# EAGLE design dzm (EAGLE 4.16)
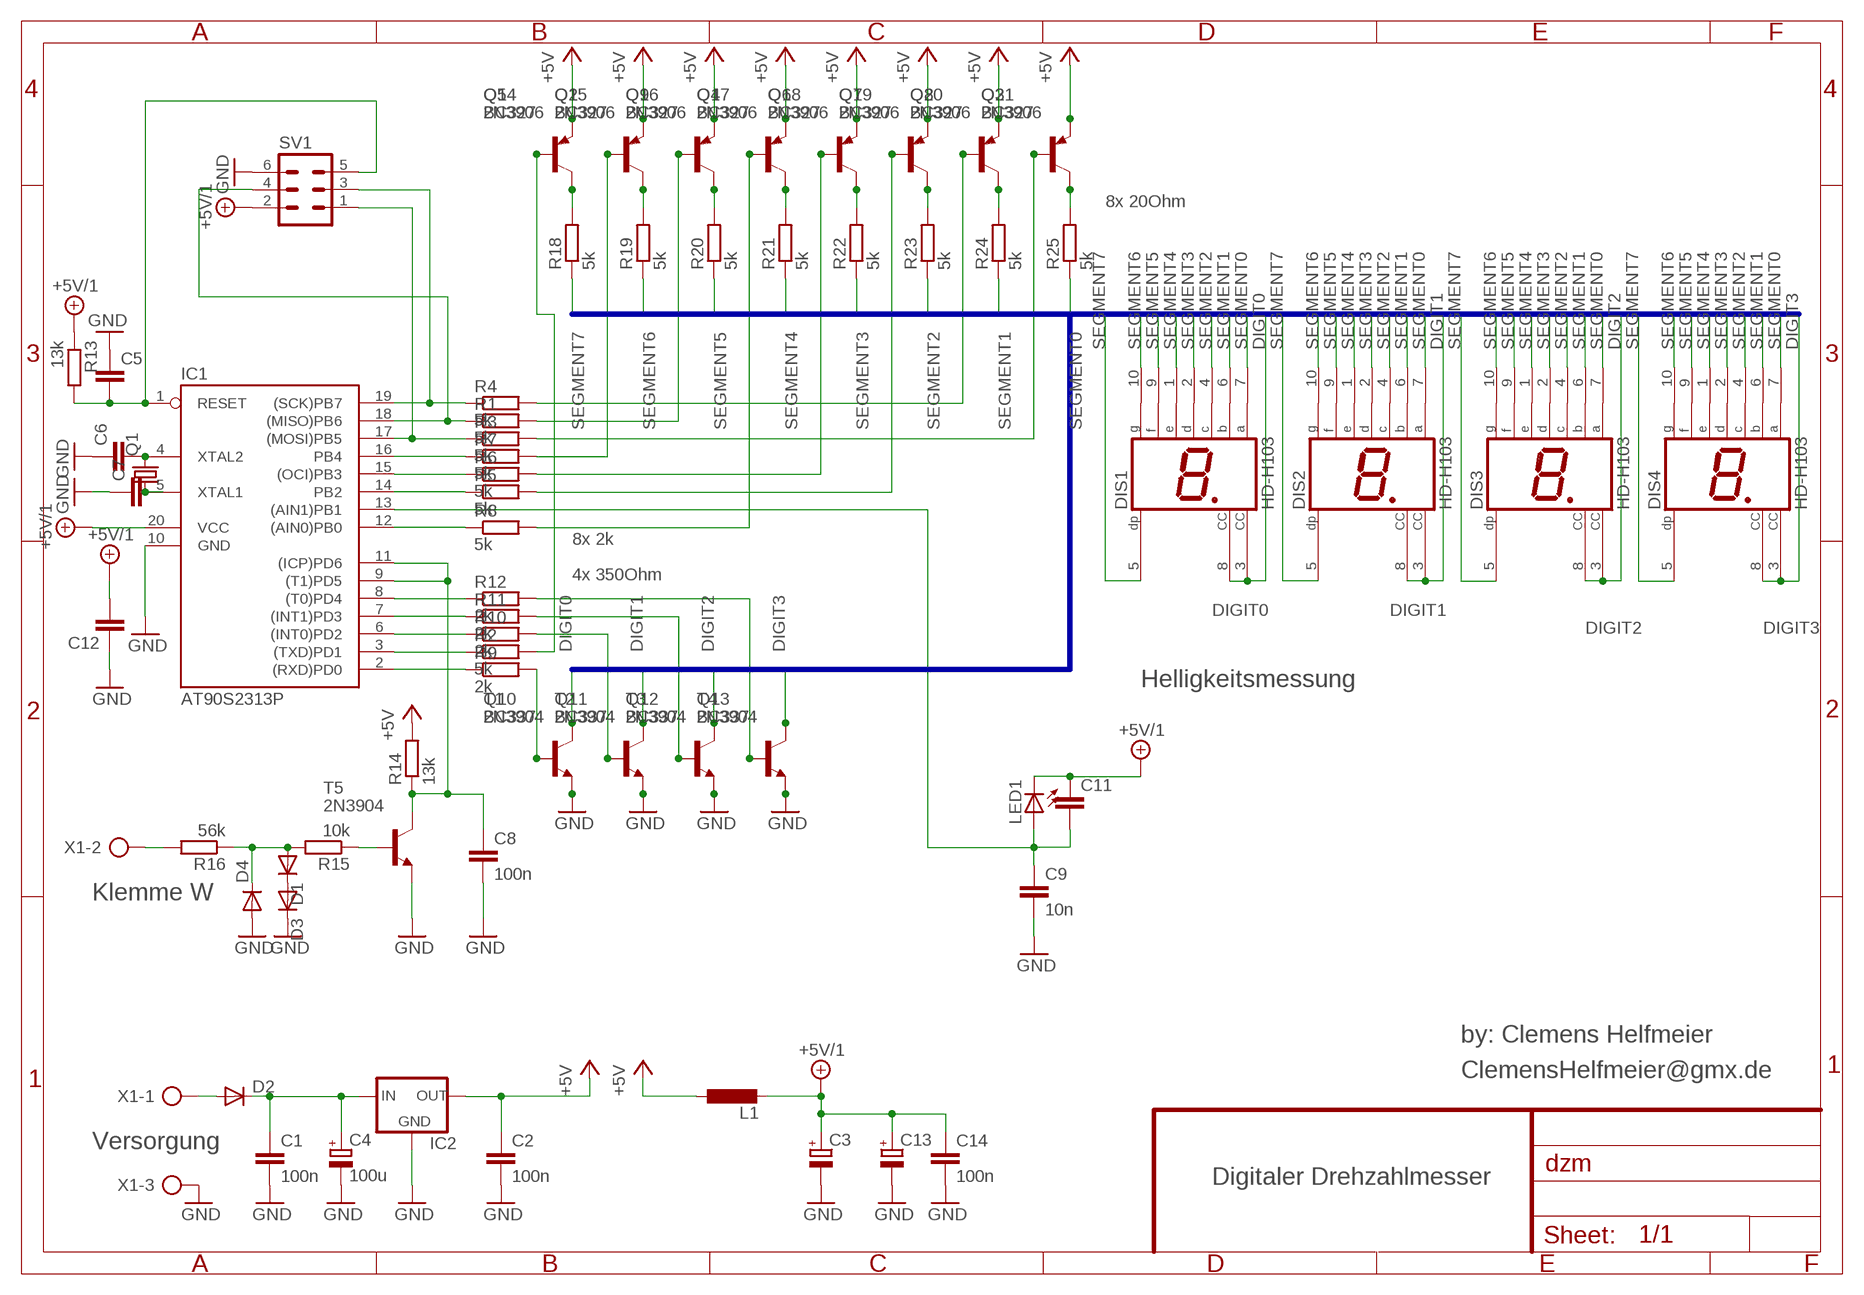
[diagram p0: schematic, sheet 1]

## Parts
C1  100n  C-EU025-024X044  [C025-024X044]
C2  100n  C-EU025-024X044  [C025-024X044]
C3  CPOL-EUE5-10.5  [E5-10,5]
C4  100u  CPOL-EUE5-13  [E5-13]
C5  C-EU025-024X044  [C025-024X044]
C6  C-EU025-024X044  [C025-024X044]
C7  C-EU025-024X044  [C025-024X044]
C8  100n  C-EU025-024X044  [C025-024X044]
C9  10n  C-EU025-024X044  [C025-024X044]
C11  C-EU050-024X044  [C050-024X044]
C12  C-EU025-024X044  [C025-024X044]
C13  CPOL-EUE2.5-7  [E2,5-7]
C14  100n  C-EU025-024X044  [C025-024X044]
D1  DIODE-D-5  [D-5]
D2  DIODE-D-7.5  [D-7.5]
D3  DIODE-D-5  [D-5]
D4  DIODE-D-5  [D-5]
DIS1  HD-H103  [HDSP-M]
DIS2  HD-H103  [HDSP-M]
DIS3  HD-H103  [HDSP-M]
DIS4  HD-H103  [HDSP-M]
IC1  AT90S2313P  [DIL20]
IC2  78XXS  [78XXS]
L1  L-EU0207/5V  [0207/5V]
LED1  LED5MM  [LED5MM]
Q1  CRYTALHC49S  [HC49/S]
Q2  2N3906  [TO92]
Q3  2N3906  [TO92]
Q4  2N3906  [TO92]
Q5  2N3906  [TO92]
Q6  2N3906  [TO92]
Q7  2N3906  [TO92]
Q8  2N3906  [TO92]
Q9  2N3906  [TO92]
Q10  BC337  [TO92]
Q11  BC337  [TO92]
Q12  BC337  [TO92]
Q13  BC337  [TO92]
Q14  BC327  [TO92]
Q15  BC327  [TO92]
Q16  BC327  [TO92]
Q17  BC327  [TO92]
Q18  BC327  [TO92]
Q19  BC327  [TO92]
Q20  BC327  [TO92]
Q21  BC327  [TO92]
R1  5k  R-EU_0207/12  [0207/12]
R2  5k  R-EU_0207/7  [0207/7]
R3  5k  R-EU_0207/12  [0207/12]
R4  5k  R-EU_0207/12  [0207/12]
R5  5k  R-EU_0207/7  [0207/7]
R6  5k  R-EU_0207/7  [0207/7]
R7  5k  R-EU_0207/10  [0207/10]
R8  5k  R-EU_0207/7  [0207/7]
R9  2k  R-EU_0207/7  [0207/7]
R10  2k  R-EU_0207/2V  [0207/2V]
R11  2k  R-EU_0207/2V  [0207/2V]
R12  2k  R-EU_0207/2V  [0207/2V]
R13  13k  R-EU_0207/7  [0207/7]
R14  13k  R-EU_0207/7  [0207/7]
R15  10k  R-EU_0207/7  [0207/7]
R16  56k  R-EU_0207/7  [0207/7]
R18  5k  R-EU_0207/2V  [0207/2V]
R19  5k  R-EU_0207/2V  [0207/2V]
R20  5k  R-EU_0207/2V  [0207/2V]
R21  5k  R-EU_0207/2V  [0207/2V]
R22  5k  R-EU_0207/2V  [0207/2V]
R23  5k  R-EU_0207/2V  [0207/2V]
R24  5k  R-EU_0207/2V  [0207/2V]
R25  5k  R-EU_0207/2V  [0207/2V]
SV1  MA03-2  [MA03-2]
T1  2N3904  [TO92]
T2  2N3904  [TO92]
T3  2N3904  [TO92]
T4  2N3904  [TO92]
T5  2N3904  [TO92]
X1  AK300/3  [AK300/3]

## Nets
+5V: C2.1 IC2.OUT L1.1 Q2.3(E) Q3.3(E) Q4.3(E) Q5.3(E) Q6.3(E) Q7.3(E) Q8.3(E) Q9.3(E) Q14.1(E) Q15.1(E) Q16.1(E) Q17.1(E) Q18.1(E) Q19.1(E) Q20.1(E) Q21.1(E) R14.2
+5V/1: C3.+ C11.1 C12.2 C13.+ C14.1 IC1.20(VCC) L1.2 LED1.K(C) R13.1 SV1.2
DIGIT0: DIS1.3(CC) DIS1.8(CC) Q10.3(C) T1.1(C)
DIGIT1: DIS2.3(CC) DIS2.8(CC) Q11.3(C) T2.1(C)
DIGIT2: DIS3.3(CC) DIS3.8(CC) Q12.3(C) T3.1(C)
DIGIT3: DIS4.3(CC) DIS4.8(CC) Q13.3(C) T4.1(C)
GND: C1.2 C2.2 C3.- C4.- C5.1 C6.1 C7.1 C8.2 C9.2 C12.1 C13.- C14.2 D3.C D4.A IC1.10(GND) IC2.GND Q10.1(E) Q11.1(E) Q12.1(E) Q13.1(E) SV1.6 T1.3(E) T2.3(E) T3.3(E) T4.3(E) T5.3(E) X1.3
N$1: D2.A X1.1
N$2: IC1.16(PB4) R7.1
N$3: IC1.17((MOSI)PB5) R3.1 SV1.1
N$4: IC1.6((INT0)PD2) R10.1
N$5: IC1.15((OCI)PB3) R6.1
N$6: IC1.14(PB2) R5.1
N$7: IC1.18((MISO)PB6) R1.1 SV1.4
N$8: IC1.12((AIN0)PB0) R8.1
N$9: IC1.7((INT1)PD3) R11.1
N$10: IC1.8((T0)PD4) R12.1
N$11: IC1.3((TXD)PD1) R2.1
N$12: Q10.2(B) R9.2 T1.2(B)
N$13: Q11.2(B) R10.2 T2.2(B)
N$14: Q12.2(B) R11.2 T3.2(B)
N$15: Q13.2(B) R12.2 T4.2(B)
N$16: Q5.2(B) Q14.2(B) R2.2
N$17: Q2.2(B) Q15.2(B) R7.2
N$18: Q3.2(B) Q21.2(B) R3.2
N$19: C1.1 C4.+ D2.C IC2.IN
N$20: Q4.2(B) Q17.2(B) R8.2
N$21: IC1.19((SCK)PB7) R4.1 SV1.3
N$22: C5.2 IC1.1(RESET) R13.2 SV1.5
N$23: C6.2 IC1.4(XTAL2) Q1.2
N$24: C7.2 IC1.5(XTAL1) Q1.1
N$25: IC1.2((RXD)PD0) R9.1
N$26: Q6.2(B) Q18.2(B) R6.2
N$27: Q7.2(B) Q19.2(B) R5.2
N$28: Q8.2(B) Q20.2(B) R4.2
N$29: Q9.2(B) Q16.2(B) R1.2
N$30: C8.1 IC1.9((T1)PD5) IC1.11((ICP)PD6) R14.1 T5.1(C)
N$31: R15.1 T5.2(B)
N$32: D1.C D3.A
N$33: R16.2 X1.2
N$34: D1.A D4.C R15.2 R16.1
N$35: C9.1 C11.2 IC1.13((AIN1)PB1) LED1.A
N$37: Q5.1(C) Q14.3(C) R18.2
N$38: Q2.1(C) Q15.3(C) R19.2
N$39: Q3.1(C) Q21.3(C) R25.2
N$40: Q4.1(C) Q17.3(C) R21.2
N$41: Q6.1(C) Q18.3(C) R22.2
N$42: Q7.1(C) Q19.3(C) R23.2
N$43: Q8.1(C) Q20.3(C) R24.2
N$44: Q9.1(C) Q16.3(C) R20.2
SEGMENT0: DIS1.7(A) DIS2.7(A) DIS3.7(A) DIS4.7(A) R25.1
SEGMENT1: DIS1.6(B) DIS2.6(B) DIS3.6(B) DIS4.6(B) R24.1
SEGMENT2: DIS1.4(C) DIS2.4(C) DIS3.4(C) DIS4.4(C) R23.1
SEGMENT3: DIS1.2(D) DIS2.2(D) DIS3.2(D) DIS4.2(D) R22.1
SEGMENT4: DIS1.1(E) DIS2.1(E) DIS3.1(E) DIS4.1(E) R21.1
SEGMENT5: DIS1.9(F) DIS2.9(F) DIS3.9(F) DIS4.9(F) R20.1
SEGMENT6: DIS1.10(G) DIS2.10(G) DIS3.10(G) DIS4.10(G) R19.1
SEGMENT7: DIS1.5(DP) DIS2.5(DP) DIS3.5(DP) DIS4.5(DP) R18.1

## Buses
DISPLAY:SEGMENT[0..7],DIGIT[0..3]

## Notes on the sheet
- 8x 20Ohm
- 8x 2k
- 4x 350Ohm
- Helligkeitsmessung
- Klemme W
- by: Clemens Helfmeier
- ClemensHelfmeier@gmx.de
- Versorgung
- Digitaler Drehzahlmesser

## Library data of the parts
C1 C2 C5-C9 C11 C12 C14 = rcl:C-EU: CAPACITOR, European symbol
C3 C4 C13 = rcl:CPOL-EU: POLARIZED CAPACITOR, European symbol
D1-D4 = diode:DIODE-: DIODE
DIS1-DIS4 = display-hp:HD-H103: LED DISPLAY 1-character 7 segment, decimal point right
IC1 = atmel:AT90S2313: MICROCONTROLLER 2 Kbytes FLASH 128 bytes SRAM 128 bytes EEPROM UART
IC2 = v-reg:78XXS: VOLTAGE REGULATOR
L1 = rcl:L-EU: INDUCTOR, European symbol
LED1 = led:LED: LED
Q1 = crystal:CRYTAL: CRYSTAL
Q2-Q9 = transistor-pnp:2N3906: PNP Transistor
Q10-Q13 = transistor-npn:BC337*: NPN Transistor
Q14-Q21 = transistor-pnp:BC327: PNP Transistor
R1-R16 R18-R25 = rcl:R-EU_: RESISTOR, European symbol
SV1 = con-lstb:MA03-2: PIN HEADER
T1-T5 = transistor:2N3904: NPN TRANSISTOR
X1 = con-ptr500:AK300/3: CONNECTOR

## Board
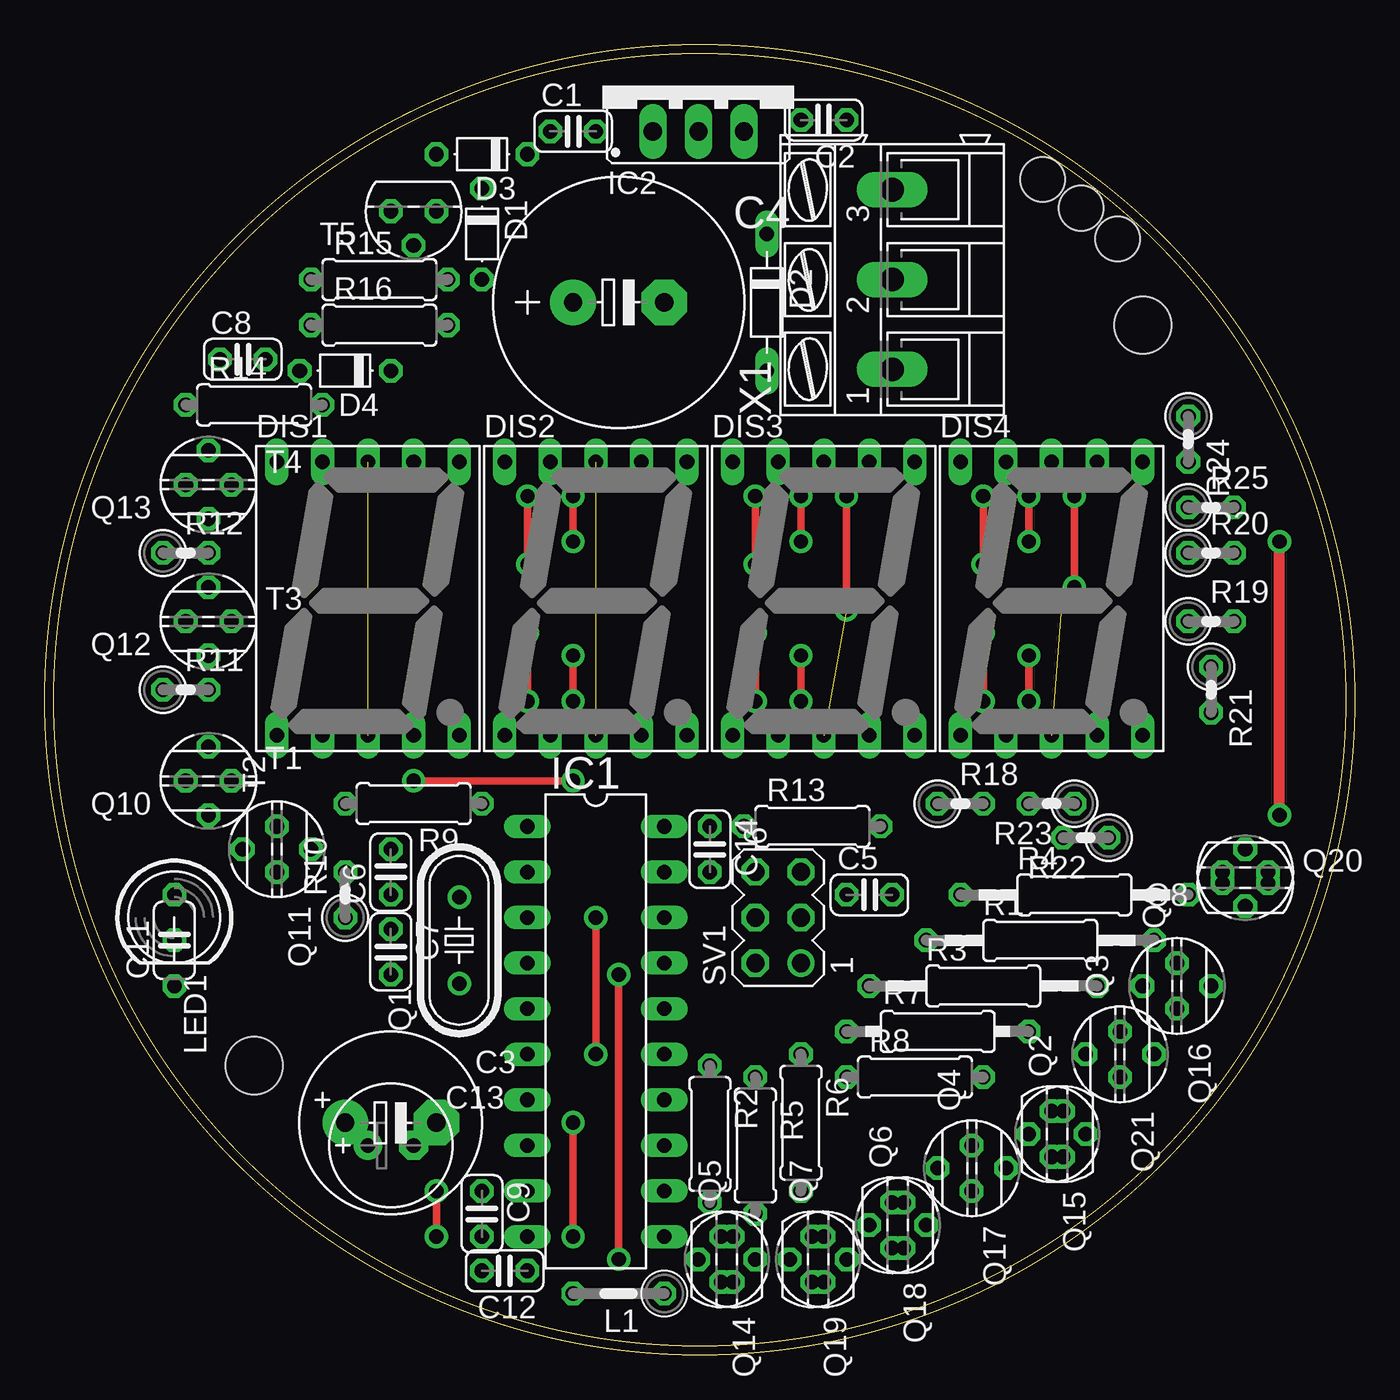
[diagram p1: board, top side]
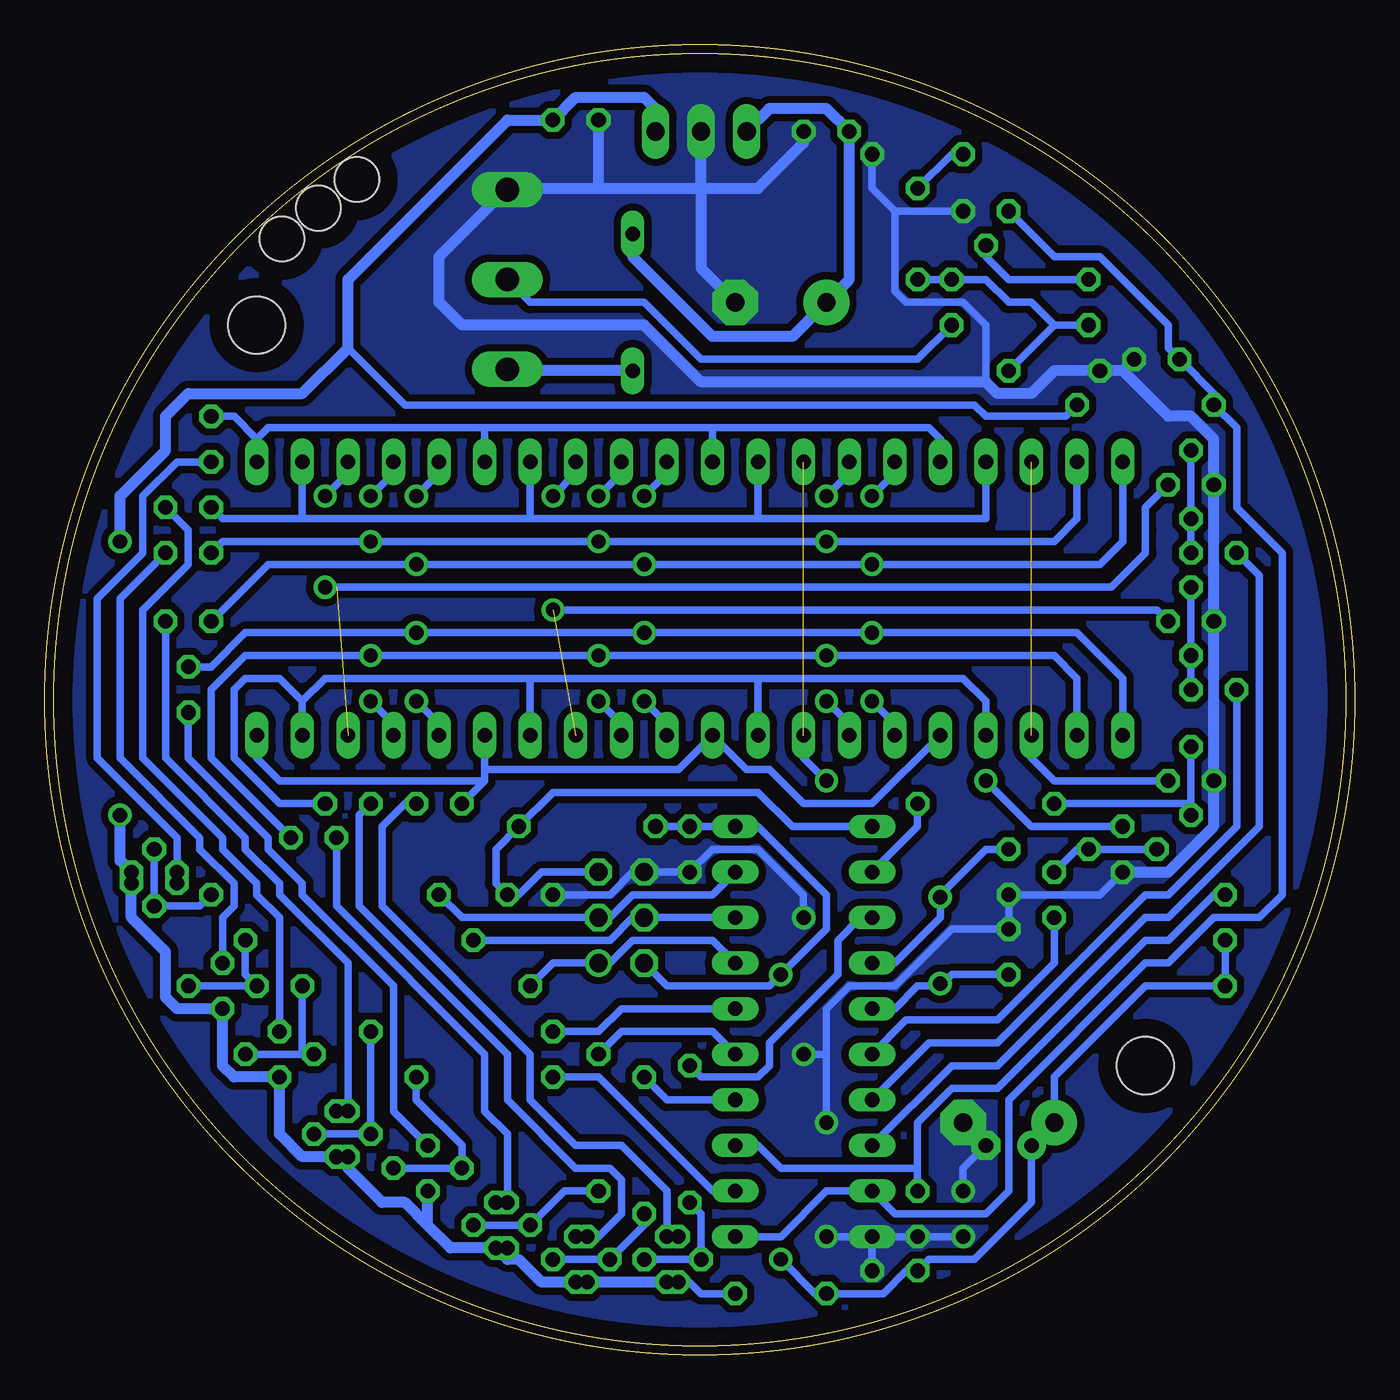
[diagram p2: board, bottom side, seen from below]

Size 73 x 73 mm. Coordinates in mm from the lower left corner, seen from the top.
Outline: circle at 36.5,36.5 radius 36.5
Outline: circle at 36.5,36.5 radius 36
Copper layers (1*16): Top 0.035mm / dielectric 1.5mm / Bottom 0.035mm
Design rules "homebrew": minimum track width 16mil, minimum drill 0.8mm, track to track 0.25mm, track to pad 0.25mm, pad to pad 0.25mm, via to via 0.25mm, smd to smd 8mil, copper to edge 40mil, drill to drill 0.2mm, minimum pad ring 0.25mm, minimum via ring 0.25mm, stop-mask expansion 0.15mm, vias tented up to drill 0mil, thermal gap 10mil
Holes 3.2 mm at 61.19,57.38 11.66,16.11
Holes 2.5 mm at 55.61,65.5 57.75,63.9 59.79,62.19

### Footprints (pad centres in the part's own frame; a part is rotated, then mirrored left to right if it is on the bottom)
C025-024X044 = drill 0.813 octagon: 1 -1.27,0; 2 1.27,0
E5-10,5 = drill 1.016 pad 2.54 round: + -2.54,0 | drill 1.016 pad 2.54 octagon: - 2.54,0
E5-13 = drill 1.016 pad 2.54 round: + -2.54,0 | drill 1.016 pad 2.54 octagon: - 2.54,0
C050-024X044 = drill 0.813 octagon: 1 -2.54,0; 2 2.54,0
E2,5-7 = drill 0.813 pad 1.6 round: + -1.27,0 | drill 0.813 pad 1.6 octagon: - 1.27,0
D-5 = drill 0.813 octagon: A 2.54,0; C -2.54,0
D-7.5 = drill 0.813 long: A 3.81,0; C -3.81,0
HDSP-M = drill 0.813 long: 1 -5.08,-7.62; 2 -2.54,-7.62; 3 0,-7.62; 4 2.54,-7.62; 5 5.08,-7.62; 6 5.08,7.62; 7 2.54,7.62; 8 0,7.62; 9 -2.54,7.62; 10 -5.08,7.62
DIL20 = drill 0.813 long: 1 -11.43,-3.81; 2 -8.89,-3.81; 3 -6.35,-3.81; 4 -3.81,-3.81; 5 -1.27,-3.81; 6 1.27,-3.81; 7 3.81,-3.81; 8 6.35,-3.81; 9 8.89,-3.81; 10 11.43,-3.81; 11 11.43,3.81; 12 8.89,3.81; 13 6.35,3.81; 14 3.81,3.81; 15 1.27,3.81; 16 -1.27,3.81; 17 -3.81,3.81; 18 -6.35,3.81; 19 -8.89,3.81; 20 -11.43,3.81
78XXS = drill 1.016 long: GND 0,-2.54; IN -2.54,-2.54; OUT 2.54,-2.54
0207/5V = drill 0.813 octagon: 1 -2.54,0; 2 2.54,0
LED5MM = drill 0.813 octagon: A -1.27,0; K 1.27,0
HC49/S = drill 0.813 round: 1 -2.413,0; 2 2.413,0
TO92 = drill 0.813 octagon: 1 1.27,0; 2 0,1.905; 3 -1.27,0
0207/12 = drill 0.813 octagon: 1 -6.35,0; 2 6.35,0
0207/7 = drill 0.813 octagon: 1 -3.81,0; 2 3.81,0
0207/10 = drill 0.813 octagon: 1 -5.08,0; 2 5.08,0
0207/2V = drill 0.813 octagon: 1 -1.27,0; 2 1.27,0
MA03-2 = drill 1.016 round: 1 -2.54,-1.27 | drill 1.016 octagon: 2 -2.54,1.27; 3 0,-1.27; 4 0,1.27; 5 2.54,-1.27; 6 2.54,1.27
AK300/3 = drill 1.321 long: 1 -5.004,0; 2 0,0; 3 5.004,0

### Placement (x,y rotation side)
C1  29.44,68.17 0 top
C2  43.41,68.81 180 top
C3  19.28,12.93 0 top
C4  31.98,58.65 0 top
C5  45.95,25.63 0 top
C6  19.28,26.9 90 top
C7  19.28,22.45 270 top
C8  11.03,55.48 0 top
C9  24.36,7.85 270 top
C11  7.21,23.09 90 top
C12  25.63,4.67 180 top
C13  19.28,11.66 0 top
C14  37.06,28.17 270 top
D1  24.36,62.46 270 top
D2  40.23,58.65 270 top
D3  24.36,66.91 180 top
D4  16.74,54.84 180 top
DIS1  18.01,42.14 0 top
DIS2  30.71,42.14 0 top
DIS3  43.41,42.14 0 top
DIS4  56.11,42.14 0 top
IC1  30.71,18.01 270 top
IC2  36.42,70.72 0 top
L1  31.98,3.41 180 top
LED1  7.21,24.36 270 top
Q1  23.09,23.09 90 top
Q2  56.74,12.29 90 top
Q3  59.92,16.74 90 top
Q4  51.66,10.39 90 top
Q5  38.33,5.31 90 top
Q6  47.85,7.21 90 top
Q7  43.41,5.31 90 top
Q8  66.91,26.9 180 top
Q9  63.09,20.55 90 top
Q10  9.12,31.98 180 top
Q11  12.93,28.17 270 top
Q12  9.12,40.87 180 top
Q13  9.12,48.49 180 top
Q14  37.7,5.31 270 top
Q15  56.11,12.29 270 top
Q16  63.09,20.55 270 top
Q17  51.66,10.39 270 top
Q18  47.22,7.21 270 top
Q19  42.77,5.31 270 top
Q20  66.91,26.27 0 top
Q21  59.92,16.74 270 top
R1  55.48,23.09 0 top
R2  37.06,12.29 270 top
R3  52.3,20.55 0 top
R4  57.38,25.63 0 top
R5  39.6,11.66 270 top
R6  42.14,12.93 270 top
R7  49.76,18.01 0 top
R8  48.49,15.47 0 top
R9  20.55,30.71 180 top
R10  16.74,25.63 90 top
R11  7.85,37.06 0 top
R12  7.85,44.68 0 top
R13  42.77,29.44 0 top
R14  11.66,52.94 0 top
R15  18.64,59.92 0 top
R16  18.64,57.38 0 top
R18  51.03,30.71 0 top
R19  65,40.87 0 top
R20  65,44.68 0 top
R21  65,37.06 270 top
R22  58.02,28.8 180 top
R23  56.11,30.71 180 top
R24  63.73,51.03 270 top
R25  65,47.22 0 top
SV1  40.87,24.36 90 top
T1  9.12,31.98 0 top
T2  12.93,28.17 90 top
T3  9.12,40.87 0 top
T4  9.12,48.49 0 top
T5  20.55,63.73 180 top
X1  47.22,59.92 90 top

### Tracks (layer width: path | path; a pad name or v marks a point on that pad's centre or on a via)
+5V  (via drill 0.8)
  Top 0.61: v68.81,30.07 v68.81,45.31
  Bottom 0.406: 56.11,56.11 52.94,52.94 21.18,52.94 20.55,52.3 16.11,52.3 R14.2 | Q5.3 Q14.1 37.06,4.04 36.42,3.41 L1.1 | Q6.3 Q18.1 | Q19.1 Q7.3 | Q15.1 Q2.3 | Q20.1 Q8.3
  Bottom 0.61: Q14.1 Q5.3 Q19.1 Q7.3 45.31,4.04 46.59,5.31 47.22,5.31 Q6.3 50.4,5.95 51.66,7.21 | v68.81,45.31 68.81,47.85 66.27,50.4 66.27,52.3 65,53.57 58.65,53.57 56.11,56.11 56.11,59.92 47.22,68.81 C2.1 43.41,70.08 39.6,70.08 38.97,69.44 IC2.OUT | 51.66,7.21 Q17.1 | 51.66,7.21 52.94,8.48 54.2,8.48 56.11,10.39 Q15.1 Q2.3 58.65,11.03 59.92,12.29 Q21.1 62.46,15.47 63.09,16.11 Q16.1 65.64,19.28 66.27,19.91 66.27,22.45 68.17,24.36 Q20.1 | v68.81,30.07 68.81,27.54 Q8.3
+5V/1  (via drill 0.8)
  Top 0.406: v31.98,5.31 v31.98,21.18
  Bottom 0.406: R13.1 C14.1 IC1.20 33.25,29.44 29.44,25.63 29.44,23.73 v31.98,21.18 32.61,20.55 38.33,20.55 SV1.2 | LED1.K C11.1 11.66,20.55 16.74,15.47 C3.+ C13.+ 18.01,8.48 21.18,5.31 23.73,5.31 C12.2 25,4.67 26.27,3.41 L1.2 30.07,3.41 v31.98,5.31
DIGIT0  (1 unrouted)
  Bottom 0.406: DIS1.3 18.01,33.25 16.74,31.98 Q10.3
DIGIT1  (via drill 0.8)  (1 unrouted)
  Top 0.406: v20.55,31.98 v29.44,31.98
  Bottom 0.406: DIS2.3 30.71,33.25 v29.44,31.98 | Q11.3 18.01,29.44 v20.55,31.98
DIGIT2  (via drill 0.8)  (1 unrouted)
  Top 0.406: v44.68,41.51 v44.68,47.85
  Bottom 0.406: DIS3.8 43.41,49.12 v44.68,47.85 | v44.68,41.51 11.03,41.51 Q12.3
DIGIT3  (via drill 0.8)  (1 unrouted)
  Top 0.406: v57.38,42.77 v57.38,47.85
  Bottom 0.406: DIS4.8 56.11,49.12 v57.38,47.85 | v57.38,42.77 56.74,42.77 13.56,42.77 11.66,44.68 11.66,45.95 11.66,47.22 Q13.3
GND  (via drill 0.8)
  Top 0.406: v29.44,6.58 v29.44,12.93 | v30.71,16.74 v30.71,24.36 | v21.82,6.58 v21.82,9.12
  Bottom 0.406: 25.63,63.73 T5.3 | D3.C 26.9,65 25.63,63.73 | 25.63,63.73 25.63,59.28 25,58.65 21.82,58.65 20.55,57.38 20.55,54.2 | C5.1 41.51,25.63 40.23,26.9 SV1.6 C14.2 35.79,28.17 33.25,28.17 30.71,25.63 v30.71,24.36 | v29.44,12.93 29.44,16.74 | 29.44,16.74 v30.71,16.74 | 29.44,16.74 29.44,19.28 28.17,20.55 25.63,20.55 22.45,23.73 C7.1 C6.1 14.2,25.63 Q11.1 | IC1.10 C9.2 v21.82,6.58 | v21.82,9.12 21.82,10.39 C13.- C3.- | IC1.10 v29.44,6.58 | IC1.10 C12.1
  Bottom 0.61: Q11.1 10.39,26.9 7.85,29.44 Q10.1 Q12.1 Q13.1 7.85,51.03 9.12,52.3 10.39,52.3 12.93,54.84 | 12.93,54.84 D4.A 16.74,54.84 18.01,53.57 19.91,53.57 20.55,54.2 36.42,54.2 39.6,57.38 49.76,57.38 51.03,58.65 51.03,61.19 47.22,65 | 12.93,54.84 C8.2 | 36.42,65 36.42,60.55 C4.- | 36.42,65 IC2.GND | 47.14,64.92 X1.3 47.22,65 | C1.2 30.71,67.54 33.25,65 36.42,65 | 47.22,65 42.14,65 | 42.14,65 36.42,65 | 42.14,65 C2.2
  pour Bottom (isolate 0.406, rank 3, no thermals): 35.79,72.62 arc90 0.23,37.06 arc90 34.52,0.23 37.06,0.23 arc90 72.62,35.79 arc90
N$1
  Bottom 0.61: X1.1 47.22,54.84 D2.A
N$2
  Bottom 0.406: IC1.16 40.87,19.28 42.14,18.01 R7.1
N$3
  Bottom 0.406: IC1.17 35.79,23.09 40.23,23.09 41.51,21.82 SV1.1 44.68,21.82 R3.1
N$4
  Bottom 0.406: R10.1 16.74,21.82 19.91,18.64 25,18.64 IC1.6
N$5
  Bottom 0.406: IC1.15 35.79,18.01 40.87,18.01 R6.1
N$6
  Bottom 0.406: IC1.14 38.33,14.2 R5.1
N$7
  Bottom 0.406: IC1.18 SV1.4 40.23,24.36 41.51,23.09 R1.1
N$8
  Bottom 0.406: IC1.12 35.79,9.12 42.14,15.47 R8.1
N$9
  Bottom 0.406: IC1.7 23.73,17.38 19.91,17.38 11.66,25.63 10.39,25.63 6.58,29.44 R11.1
N$10
  Bottom 0.406: R12.1 5.31,43.41 5.31,29.44 10.39,24.36 11.66,24.36 19.91,16.11 22.45,16.11 IC1.8
N$11
  Bottom 0.406: R2.1 36.42,15.47 33.25,15.47 32.61,16.11 32.61,17.38 28.8,21.18 28.8,23.09 27.54,24.36 IC1.3
N$12
  Bottom 0.406: Q10.2 9.12,30.71 | 9.12,30.71 T1.2 | 9.12,30.71 R9.2
N$13
  Bottom 0.406: R10.2 15.47,28.17 Q11.2 T2.2
N$14
  Bottom 0.406: R11.2 Q12.2 9.12,40.87 T3.2
N$15
  Bottom 0.406: Q13.2 R12.2 Q13.2 | Q13.2 T4.2
N$16
  Bottom 0.406: R2.2 36.42,7.85 Q5.2 Q14.2
N$17
  Bottom 0.406: R7.2 Q2.2 Q15.2
N$18
  Bottom 0.406: Q3.2 58.65,16.74 | 58.65,16.74 Q21.2 | 58.65,16.74 R3.2
N$19
  Bottom 0.61: IC2.IN 32.61,69.44 29.44,69.44 C1.1 28.17,59.92 C4.+ 31.34,56.74 35.79,56.74 40.23,61.19 D2.C
N$20
  Bottom 0.406: R8.2 52.3,14.2 49.76,11.66 Q4.2 Q17.2
N$21
  Bottom 0.406: IC1.19 35.79,25.63 40.23,25.63 41.51,24.36 SV1.3 49.76,24.36 R4.1
N$22
  Bottom 0.406: IC1.1 31.34,29.44 33.25,31.34 44.68,31.34 R13.2 47.85,28.17 47.85,26.27 C5.2 46.59,25.63 45.31,26.9 SV1.5
N$23
  Bottom 0.406: C6.2 20.55,28.17 23.09,25.63 Q1.2 23.09,24.36 25.63,21.82 IC1.4
N$24
  Bottom 0.406: C7.2 22.45,21.18 23.09,20.55 | IC1.5 25.63,19.28 24.36,20.55 23.09,20.55 | 23.09,20.55 Q1.1
N$25
  Bottom 0.406: IC1.2 24.36,29.44 R9.1
N$26
  Bottom 0.406: R6.2 44.05,9.12 Q6.2 Q18.2
N$27
  Bottom 0.406: Q19.2 Q7.2 39.6,7.21 R5.2
N$28
  Bottom 0.406: Q20.2 Q8.2 64.37,25 R4.2
N$29
  Bottom 0.406: R1.2 61.83,21.18 Q9.2 Q16.2
N$30
  Bottom 0.406: IC1.11 31.98,6.58 29.44,9.12 IC1.9 25.63,7.85 20.55,7.85 19.28,9.12 19.28,14.2 11.66,21.82 10.39,21.82 7.85,24.36 5.31,24.36 4.04,25.63 4.04,44.68 6.58,47.22 6.58,51.66 R14.1 7.85,53.57 C8.1 10.39,56.11 10.39,57.38 14.2,61.19 16.74,61.19 T5.1
N$31
  Bottom 0.406: R15.1 19.28,59.92 20.55,61.19 T5.2
N$32
  Bottom 0.406: D3.A 22.45,66.91 D1.C
N$33
  Bottom 0.406: R16.2 24.36,55.48 36.42,55.48 39.6,58.65 45.95,58.65 X1.2
N$34
  Bottom 0.406: R16.1 16.74,57.38 | 16.74,57.38 D4.C | D1.A R15.2 20.55,59.92 19.28,58.65 18.01,58.65 16.74,57.38
N$35
  Bottom 0.406: IC1.13 33.25,11.66 31.98,10.39 24.36,10.39 | C11.2 7.85,25.63 10.39,23.09 11.66,23.09 19.91,14.84 22.45,14.84 24.36,12.93 24.36,10.39 | 24.36,10.39 C9.1
N$37
  Bottom 0.406: R18.2 52.94,30.71 54.2,29.44 54.2,25 45.95,16.74 45.95,14.2 43.41,11.66 40.87,11.66 38.33,9.12 Q5.1 Q14.3
N$38
  Bottom 0.406: R19.2 66.27,33.25 61.83,28.8 61.83,28.17 59.92,26.27 59.92,25.63 56.11,21.82 Q15.3 Q2.1
N$39
  Bottom 0.406: R25.2 65,45.95 65,44.05 67.54,41.51 67.54,33.25 63.09,28.8 63.09,28.17 61.19,26.27 61.19,25.63 59.92,24.36 Q21.3
N$40
  Bottom 0.406: R21.2 65,33.25 60.55,28.8 60.55,28.17 58.65,26.27 58.65,25.63 53.57,20.55 53.57,13.56 Q17.3
N$41
  Bottom 0.406: R22.2 56.74,25 48.49,16.74 48.49,13.56 47.22,12.29 Q18.3 Q6.1
N$42
  Bottom 0.406: R23.2 55.48,30.07 55.48,25 47.22,16.74 47.22,14.2 43.41,10.39 41.51,10.39 40.87,9.76 40.87,7.85 42.14,6.58 Q19.3 Q7.1
N$43
  Bottom 0.406: R24.2 65.64,49.76 67.54,47.85 67.54,44.68 70.08,42.14 70.08,33.25 65.64,28.8 Q8.1 | Q8.1 Q20.3 Q8.1
N$44
  Bottom 0.406: R20.2 68.81,42.14 68.81,33.25 64.37,28.8 64.37,28.17 62.46,26.27 62.46,25 63.09,24.36 Q16.3
SEGMENT0
  Bottom 0.406: 45.95,46.59 58.65,46.59 | 45.95,46.59 DIS3.7 | 33.25,46.59 45.95,46.59 | 33.25,46.59 DIS2.7 | 33.25,46.59 20.55,46.59 DIS1.7 | 58.65,46.59 DIS4.7 | 58.65,46.59 63.09,46.59 R25.1
SEGMENT1
  Bottom 0.406: 35.79,51.66 48.49,51.66 | 48.49,51.66 60.55,51.66 61.19,51.03 | 48.49,51.66 DIS3.6 | 35.79,51.66 DIS2.6 | 35.79,51.66 23.73,51.66 23.09,51.03 DIS1.6 | 61.19,51.03 DIS4.6 | 61.19,51.03 62.46,52.3 R24.1
SEGMENT2
  Bottom 0.406: DIS1.4 20.55,36.42 21.82,37.7 33.25,37.7 | 33.25,37.7 DIS2.4 | 33.25,37.7 45.95,37.7 | 45.95,37.7 DIS3.4 | 45.95,37.7 57.38,37.7 58.65,36.42 | 58.65,36.42 DIS4.4 | 58.65,36.42 59.92,37.7 61.83,37.7 62.46,37.06 62.46,33.25 59.92,30.71 R23.1
SEGMENT3  (via drill 0.8)
  Top 0.406: v54.84,38.97 v54.84,36.42 | v42.14,38.97 v42.14,36.42 | v29.44,38.97 v29.44,36.42
  Bottom 0.406: DIS1.2 15.47,37.7 16.74,38.97 v29.44,38.97 v42.14,38.97 v54.84,38.97 61.83,38.97 63.73,37.06 63.73,33.25 R22.1 | v54.84,36.42 53.57,35.16 DIS4.2 | v42.14,36.42 40.87,35.16 DIS3.2 | v29.44,36.42 28.17,35.16 DIS2.2
SEGMENT4  (via drill 0.8)
  Top 0.406: v52.3,40.23 v52.3,36.42 | v39.6,40.23 v39.6,36.42 | v26.9,40.23 v26.9,36.42
  Bottom 0.406: DIS1.1 12.93,37.7 15.47,40.23 v26.9,40.23 v39.6,40.23 v52.3,40.23 61.83,40.23 63.73,38.33 R21.1 | v52.3,36.42 51.03,35.16 DIS4.1 | v39.6,36.42 38.33,35.16 DIS3.1 | v26.9,36.42 25.63,35.16 DIS2.1
SEGMENT5  (via drill 0.8)
  Top 0.406: v54.84,45.31 v54.84,47.85 | v42.14,45.31 v42.14,47.85 | v29.44,45.31 v29.44,47.85
  Bottom 0.406: v54.84,47.85 53.57,49.12 DIS4.9 | v42.14,47.85 40.87,49.12 DIS3.9 | v29.44,47.85 28.17,49.12 DIS2.9 | DIS1.9 15.47,46.59 16.74,45.31 v29.44,45.31 v42.14,45.31 v54.84,45.31 63.09,45.31 R20.1
SEGMENT6  (via drill 0.8)
  Top 0.406: v52.3,44.05 v52.3,47.85 | v39.6,44.05 v39.6,47.85 | v26.9,44.05 v26.9,47.85
  Bottom 0.406: DIS1.10 12.93,45.31 14.2,44.05 v26.9,44.05 v39.6,44.05 v52.3,44.05 60.55,44.05 R19.1 | v52.3,47.85 51.03,49.12 DIS4.10 | v39.6,47.85 38.33,49.12 DIS3.10 | v26.9,47.85 25.63,49.12 DIS2.10
SEGMENT7
  Bottom 0.406: 48.49,32.61 48.49,31.98 | 48.49,32.61 DIS3.5 | 48.49,31.98 59.92,31.98 61.19,33.25 DIS4.5 | DIS1.5 26.9,30.71 30.71,30.71 32.61,32.61 33.88,32.61 DIS2.5 37.7,32.61 48.49,32.61 | 48.49,31.98 R18.1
